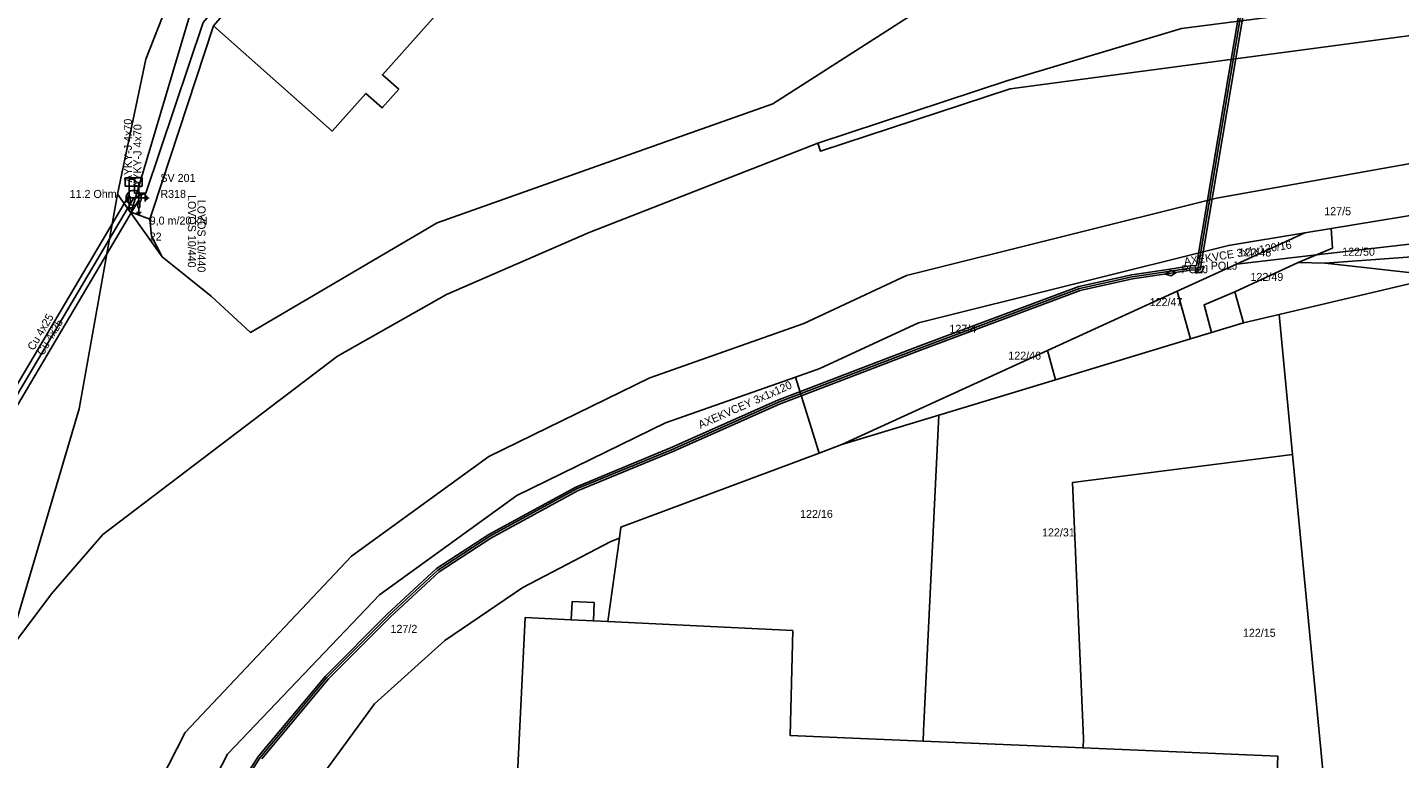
# Model space of a CAD drawing. Extents: x -793400 to -756198, y -1074141 to -1042963.
# Drawn here: x -783476.3 to -783347.8, y -1064939.5 to -1064870.9 of the extents above; entities that cross this region are included whole.
import ezdxf

# ---------------------------------------------------------------- set-up
doc = ezdxf.new("R2010")
doc.units = 0
for name, color, linetype in [('Parcela', 7, 'Continuous'), ('PB nn', 7, 'Continuous'), ('Popiskový text - Parcela', 7, 'Continuous'), ('Popiskový text - PB nn - sk_1 - SJZ', 7, 'Continuous'), ('Popiskový text - PB nn - sk_1 - Výška_Tahové namáhání', 7, 'Continuous'), ('Popiskový text - Rozpojovací skříň nn - SJZ', 7, 'Continuous'), ('Popiskový text - Rozpojovací skříň nn - Typ', 7, 'Continuous'), ('Popiskový text - Spojka vn - Typ', 7, 'Continuous'), ('Popiskový text - Svodič nn - Typ', 7, 'Continuous'), ('Popiskový text - Uzemnění - Odpor', 7, 'Continuous'), ('Popiskový text - Vedení nn svod', 7, 'Continuous'), ('Popiskový text - Vedení nn venkovní', 7, 'Continuous'), ('Popiskový text - Vedení vn kabelové', 7, 'Continuous'), ('Skříň', 7, 'Continuous'), ('Spojka vn', 7, 'Continuous'), ('Spojnice nn', 7, 'Continuous'), ('Spojnice vn', 7, 'Continuous'), ('Stavební objekt', 7, 'Continuous'), ('Svodič nn', 7, 'Continuous'), ('Uzemnění', 7, 'Continuous'), ('Vedení 22 kV kabelové', 7, 'Continuous'), ('Vedení nn kabelové', 7, 'Continuous'), ('Vedení nn svod', 7, 'Continuous'), ('Vedení nn venkovní', 7, 'Continuous')]:
    doc.layers.add(name, color=color, linetype=linetype)

msp = doc.modelspace()

# ---------------------------------------------------------------- linework, layer by layer
at = {"layer": 'Parcela'}
for points in [[(-783338.48, -1064697.96), (-783349.27, -1064716.7), (-783367.16, -1064741.51), (-783384.84, -1064768.74), (-783393.05, -1064780.33), (-783390.82, -1064782.2), (-783435.82, -1064826.87), (-783453.88, -1064848.76), (-783461.77, -1064865.05), (-783465.25, -1064873.91), (-783467.9, -1064886.57), (-783471.49, -1064906.69), (-783478.28, -1064929.62), (-783482.83, -1064940.99)], [(-783482.83, -1064940.99), (-783478.28, -1064929.62), (-783474.07, -1064924.03), (-783469.27, -1064918.46), (-783447.3, -1064901.74), (-783437.08, -1064895.97), (-783423.7, -1064890.15), (-783407.72, -1064883.89), (-783402.29, -1064881.78), (-783402.03, -1064882.54), (-783384.26, -1064876.67), (-783335.01, -1064870.13), (-783304.09, -1064866.02), (-783285.91, -1064866.45), (-783278.18, -1064867.77), (-783223.32, -1064876.5)], [(-783227.58, -1064889.71), (-783274.38, -1064881.1), (-783287.03, -1064879.4), (-783307.17, -1064880.57), (-783332.97, -1064881.2), (-783364.93, -1064886.92), (-783393.97, -1064894.19), (-783403.59, -1064898.67), (-783418.04, -1064903.77), (-783433.11, -1064911.15), (-783445.96, -1064920.48), (-783461.55, -1064937.01), (-783469.34, -1064952.28)], [(-783469.34, -1064952.28), (-783461.55, -1064937.01), (-783445.96, -1064920.48), (-783433.11, -1064911.15), (-783418.04, -1064903.77), (-783403.59, -1064898.67), (-783393.97, -1064894.19), (-783364.93, -1064886.92), (-783332.97, -1064881.2), (-783307.17, -1064880.57), (-783287.03, -1064879.4), (-783274.38, -1064881.1), (-783227.58, -1064889.71)], [(-783225.68, -1064895.58), (-783274.99, -1064885.59), (-783280.75, -1064884.81), (-783287.64, -1064883.89), (-783306.72, -1064885.08), (-783332, -1064887.64), (-783332.16, -1064886.15), (-783354.2, -1064889.78), (-783356.67, -1064890.19), (-783363.82, -1064891.36), (-783392.86, -1064898.63), (-783402.1, -1064902.9), (-783404.39, -1064903.71), (-783416.55, -1064908), (-783430.48, -1064914.8), (-783443.35, -1064924.13), (-783457.58, -1064939.04), (-783464.9, -1064953.22)], [(-783353.28, -1064958.14), (-783357.81, -1064910.97), (-783359.07, -1064897.84), (-783343.83, -1064894.26), (-783331.24, -1064891.31), (-783281.17, -1064887.87), (-783279.74, -1064888.31), (-783222.97, -1064905.78)], [(-783464.9, -1064953.22), (-783457.58, -1064939.04), (-783443.35, -1064924.13), (-783430.48, -1064914.8), (-783416.55, -1064908), (-783404.39, -1064903.71), (-783402.17, -1064910.83), (-783420.73, -1064917.76), (-783420.88, -1064918.79), (-783421.67, -1064919.12), (-783429.93, -1064923.44), (-783437.22, -1064928.4), (-783443.83, -1064934.34), (-783449.41, -1064942)], [(-783449.41, -1064942), (-783443.83, -1064934.34), (-783437.22, -1064928.4), (-783429.93, -1064923.44), (-783421.67, -1064919.12), (-783420.88, -1064918.79), (-783421.96, -1064926.63), (-783423.31, -1064926.56), (-783423.23, -1064924.85), (-783425.3, -1064924.75), (-783425.39, -1064926.46), (-783429.7, -1064926.25), (-783430.41, -1064940.93)]]:
    msp.add_lwpolyline(points, dxfattribs=at)
for points in [[(-783385.6, -1064832.92), (-783375.04, -1064846.09), (-783368.94, -1064842.22), (-783364, -1064850.02), (-783360.4, -1064848.81), (-783374.34, -1064857.56), (-783381.42, -1064862.01), (-783383.2, -1064863.13), (-783391.14, -1064868.23), (-783406.49, -1064878.08), (-783414.73, -1064881.01), (-783437.94, -1064889.26), (-783455.45, -1064899.52), (-783459.11, -1064896.13), (-783463.71, -1064892.42), (-783464.71, -1064890.5), (-783464.87, -1064888.91), (-783464.59, -1064888.07), (-783458.89, -1064870.77), (-783415.27, -1064820.68), (-783417.8, -1064816.8), (-783413.58, -1064811.55), (-783393.24, -1064823.15), (-783383.11, -1064830.7)], [(-783417.8, -1064816.8), (-783415.27, -1064820.68), (-783417.18, -1064818.99), (-783461.16, -1064869.86), (-783466.61, -1064888.26), (-783464.87, -1064888.91), (-783464.71, -1064890.5), (-783463.71, -1064892.42), (-783467.9, -1064886.57), (-783465.25, -1064873.91), (-783461.77, -1064865.05), (-783453.88, -1064848.76), (-783451.28, -1064850.75), (-783448.79, -1064853.49)], [(-783464.59, -1064888.07), (-783464.87, -1064888.91), (-783466.61, -1064888.26), (-783461.16, -1064869.86), (-783417.18, -1064818.99), (-783415.27, -1064820.68), (-783458.89, -1064870.77)], [(-783437.08, -1064895.97), (-783447.3, -1064901.74), (-783469.27, -1064918.46), (-783474.07, -1064924.03), (-783478.28, -1064929.62), (-783471.49, -1064906.69), (-783467.9, -1064886.57), (-783463.71, -1064892.42), (-783459.11, -1064896.13), (-783455.45, -1064899.52), (-783437.94, -1064889.26), (-783414.73, -1064881.01), (-783406.49, -1064878.08), (-783391.14, -1064868.23), (-783383.2, -1064863.13), (-783381.42, -1064862.01), (-783374.34, -1064857.56), (-783360.4, -1064848.81), (-783352.38, -1064869), (-783368.2, -1064871.03), (-783384.5, -1064875.9), (-783402.29, -1064881.78), (-783407.72, -1064883.89), (-783423.7, -1064890.15)], [(-783269.29, -1064864.07), (-783252.64, -1064867.19), (-783241.36, -1064869.64), (-783217.15, -1064873.79), (-783212.94, -1064874.09), (-783223.32, -1064876.5), (-783278.18, -1064867.77), (-783285.91, -1064866.45), (-783304.09, -1064866.02), (-783335.01, -1064870.13), (-783384.26, -1064876.67), (-783402.03, -1064882.54), (-783402.29, -1064881.78), (-783384.5, -1064875.9), (-783368.2, -1064871.03), (-783352.38, -1064869), (-783335.67, -1064866.45), (-783335.87, -1064864.4), (-783303.98, -1064861.03), (-783285.8, -1064861.46), (-783277.41, -1064862.75)], [(-783280.75, -1064884.81), (-783279.77, -1064888.22), (-783279.74, -1064888.31), (-783281.17, -1064887.87), (-783331.24, -1064891.31), (-783354.76, -1064893.04), (-783357.29, -1064892.97), (-783355.58, -1064892.25), (-783339.48, -1064890.4), (-783284.2, -1064887.63)], [(-783284.2, -1064887.63), (-783339.48, -1064890.4), (-783355.58, -1064892.25), (-783354.08, -1064891.62), (-783354.2, -1064889.78), (-783332.16, -1064886.15), (-783332, -1064887.64), (-783306.72, -1064885.08), (-783287.64, -1064883.89), (-783280.75, -1064884.81)], [(-783400.04, -1064910.03), (-783402.17, -1064910.83), (-783404.39, -1064903.71), (-783402.1, -1064902.9), (-783392.86, -1064898.63), (-783363.82, -1064891.36), (-783356.67, -1064890.19), (-783363.06, -1064893.11), (-783368.63, -1064895.66), (-783380.77, -1064901.21)], [(-783355.58, -1064892.25), (-783363.06, -1064893.11), (-783356.67, -1064890.19), (-783354.2, -1064889.78), (-783354.08, -1064891.62)], [(-783331.24, -1064891.31), (-783343.83, -1064894.26), (-783354.76, -1064893.04)], [(-783365.39, -1064899.53), (-783367.37, -1064900.13), (-783368.63, -1064895.66), (-783363.06, -1064893.11), (-783355.58, -1064892.25), (-783357.29, -1064892.97), (-783363.23, -1064895.71), (-783366.1, -1064896.94)], [(-783359.07, -1064897.84), (-783362.4, -1064898.62), (-783363.23, -1064895.71), (-783357.29, -1064892.97), (-783354.76, -1064893.04), (-783343.83, -1064894.26)], [(-783367.37, -1064900.13), (-783380.01, -1064903.96), (-783380.77, -1064901.21), (-783368.63, -1064895.66)], [(-783362.4, -1064898.62), (-783365.39, -1064899.53), (-783366.1, -1064896.94), (-783363.23, -1064895.71)], [(-783377.4, -1064937.59), (-783377.44, -1064938.46), (-783392.43, -1064937.82), (-783392.38, -1064936.86), (-783390.94, -1064907.27), (-783380.01, -1064903.96), (-783367.37, -1064900.13), (-783365.39, -1064899.53), (-783362.4, -1064898.62), (-783359.07, -1064897.84), (-783357.81, -1064910.97), (-783378.43, -1064913.59)], [(-783390.94, -1064907.27), (-783400.04, -1064910.03), (-783380.77, -1064901.21), (-783380.01, -1064903.96)], [(-783392.38, -1064936.86), (-783392.43, -1064937.82), (-783404.88, -1064937.3), (-783404.64, -1064927.47), (-783421.96, -1064926.63), (-783420.88, -1064918.79), (-783420.73, -1064917.76), (-783402.17, -1064910.83), (-783400.04, -1064910.03), (-783390.94, -1064907.27)], [(-783356.71, -1064964.98), (-783360.26, -1064964.99), (-783359.2, -1064939.23), (-783377.44, -1064938.46), (-783377.4, -1064937.59), (-783378.43, -1064913.59), (-783357.81, -1064910.97), (-783353.28, -1064958.14), (-783354.18, -1064962.02)], [(-783423.23, -1064924.85), (-783423.31, -1064926.56), (-783421.96, -1064926.63), (-783404.64, -1064927.47), (-783404.88, -1064937.3), (-783392.43, -1064937.82), (-783377.44, -1064938.46), (-783359.2, -1064939.23), (-783360.26, -1064964.99), (-783360.34, -1064966.94), (-783408.79, -1064964.93), (-783408.66, -1064962.07), (-783416.86, -1064961.75), (-783416.9, -1064962.62), (-783419.02, -1064962.53), (-783418.98, -1064961.67), (-783431.4, -1064961.19), (-783430.84, -1064949.72), (-783433.81, -1064949.58), (-783433.38, -1064940.79), (-783430.41, -1064940.93), (-783429.7, -1064926.25), (-783425.39, -1064926.46), (-783425.3, -1064924.75)]]:
    msp.add_lwpolyline(points, close=True, dxfattribs=at)
at = {"layer": 'PB nn'}
msp.add_line((-783465.67, -1064886.91), (-783467.09, -1064886.91), dxfattribs=at)
for start, end in [(0, 180), (180, 0)]:
    msp.add_arc((-783466.38, -1064886.91), 0.709, start, end, dxfattribs=at)
at = {"layer": 'Skříň'}
msp.add_lwpolyline([(-783467.17, -1064885.02), (-783465.59, -1064885.02), (-783465.59, -1064885.8), (-783467.17, -1064885.8)], close=True, dxfattribs=at)
at = {"layer": 'Spojka vn'}
for points in [[(-783368.72, -1064893.89), (-783369.26, -1064893.72), (-783369.71, -1064894.05), (-783369.18, -1064894.22)], [(-783366.1, -1064893.31), (-783366.64, -1064893.45), (-783366.86, -1064893.97), (-783366.32, -1064893.83)]]:
    msp.add_lwpolyline(points, close=True, dxfattribs=at)
at = {"layer": 'Spojnice nn'}
msp.add_line((-783483.8, -1064916.34), (-783466.38, -1064886.91), dxfattribs=at)
msp.add_lwpolyline([(-783466.38, -1064886.91), (-783465.23, -1064886.46), (-783459.87, -1064870.48), (-783448.33, -1064856.95), (-783441.33, -1064848.51)], dxfattribs=at)
at = {"layer": 'Spojnice vn'}
for points in [[(-783362.08, -1064866.35), (-783366.65, -1064893.45)], [(-783369.25, -1064893.77), (-783372.84, -1064894.32), (-783377.78, -1064895.4), (-783392.73, -1064901), (-783405.96, -1064906.06), (-783416, -1064910.52), (-783424.88, -1064914.19), (-783433.01, -1064918.63), (-783437.9, -1064921.81), (-783442.48, -1064926.06), (-783448.27, -1064931.87), (-783454.54, -1064939.37), (-783458.76, -1064945.94)], [(-783366.65, -1064893.45), (-783367.39, -1064893.48), (-783369.25, -1064893.77)]]:
    msp.add_lwpolyline(points, dxfattribs=at)
at = {"layer": 'Stavební objekt'}
for points in [[(-783397.33, -1064836.53), (-783406.3, -1064847), (-783413.04, -1064841.14), (-783420.03, -1064849.51), (-783415.73, -1064853.11), (-783422.67, -1064861.15), (-783427.04, -1064857.37), (-783443.08, -1064875.37), (-783441.55, -1064876.73), (-783443.1, -1064878.47), (-783444.63, -1064877.11), (-783447.79, -1064880.65), (-783458.89, -1064870.77), (-783415.27, -1064820.68)], [(-783360.26, -1064964.99), (-783360.34, -1064966.94), (-783408.79, -1064964.93), (-783408.66, -1064962.07), (-783416.86, -1064961.75), (-783418.98, -1064961.67), (-783431.4, -1064961.19), (-783430.84, -1064949.72), (-783430.41, -1064940.93), (-783429.7, -1064926.25), (-783425.39, -1064926.46), (-783423.31, -1064926.56), (-783421.96, -1064926.63), (-783404.64, -1064927.47), (-783404.88, -1064937.3), (-783392.43, -1064937.82), (-783377.44, -1064938.46), (-783359.2, -1064939.23)]]:
    msp.add_lwpolyline(points, close=True, dxfattribs=at)
at = {"layer": 'Svodič nn'}
for p, q in [((-783466.9, -1064887.36), (-783466.9, -1064886.77)), ((-783466.9, -1064886.77), (-783466.7, -1064886.77)), ((-783466.7, -1064887.36), (-783466.9, -1064887.36)), ((-783466.8, -1064886.64), (-783466.8, -1064886.84)), ((-783466.8, -1064887.36), (-783466.8, -1064887.84)), ((-783466.7, -1064886.77), (-783466.7, -1064887.36)), ((-783466, -1064887.81), (-783466, -1064887.22)), ((-783466, -1064887.22), (-783465.8, -1064887.22)), ((-783465.9, -1064887.08), (-783465.9, -1064887.29)), ((-783465.8, -1064887.22), (-783465.8, -1064887.81)), ((-783467.02, -1064887.84), (-783466.58, -1064887.84)), ((-783466.94, -1064887.94), (-783466.66, -1064887.94)), ((-783466.85, -1064888.05), (-783466.75, -1064888.05)), ((-783466.12, -1064888.29), (-783465.68, -1064888.29)), ((-783466.04, -1064888.38), (-783465.76, -1064888.39)), ((-783465.8, -1064887.81), (-783466, -1064887.81)), ((-783465.95, -1064888.49), (-783465.85, -1064888.49)), ((-783465.9, -1064887.81), (-783465.9, -1064888.29))]:
    msp.add_line(p, q, dxfattribs=at)
for points in [[(-783466.8, -1064886.95), (-783466.73, -1064886.84), (-783466.87, -1064886.84)], [(-783465.9, -1064887.39), (-783465.83, -1064887.29), (-783465.97, -1064887.29)]]:
    msp.add_lwpolyline(points, close=True, dxfattribs=at)
at = {"layer": 'Uzemnění'}
for p, q in [((-783465.99, -1064886.91), (-783465.3, -1064886.91)), ((-783465.3, -1064887.26), (-783465.3, -1064886.56)), ((-783465.21, -1064887.13), (-783465.21, -1064886.69)), ((-783465.11, -1064887.05), (-783465.11, -1064886.77)), ((-783465, -1064886.96), (-783465, -1064886.86))]:
    msp.add_line(p, q, dxfattribs=at)
at = {"layer": 'Vedení 22 kV kabelové'}
for points in [[(-783362.28, -1064866.3), (-783366.82, -1064893.25), (-783367.41, -1064893.28), (-783369.28, -1064893.58), (-783372.88, -1064894.12), (-783377.84, -1064895.2), (-783392.81, -1064900.81), (-783406.04, -1064905.88), (-783416.08, -1064910.34), (-783424.96, -1064914.01), (-783433.11, -1064918.46), (-783438.02, -1064921.65), (-783442.62, -1064925.92), (-783448.41, -1064931.73), (-783454.7, -1064939.25), (-783458.94, -1064945.85)], [(-783361.89, -1064866.39), (-783366.48, -1064893.64)], [(-783369.22, -1064893.97), (-783372.8, -1064894.51), (-783377.72, -1064895.59), (-783392.66, -1064901.18), (-783405.88, -1064906.25), (-783415.92, -1064910.71), (-783424.79, -1064914.37), (-783432.91, -1064918.81), (-783437.77, -1064921.97), (-783442.34, -1064926.21), (-783448.12, -1064932), (-783454.38, -1064939.49)], [(-783366.48, -1064893.64), (-783367.37, -1064893.68), (-783369.22, -1064893.97)]]:
    msp.add_lwpolyline(points, dxfattribs=at)
at = {"layer": 'Vedení nn kabelové'}
msp.add_lwpolyline([(-783466.29, -1064885.61), (-783466.29, -1064886.46), (-783465.23, -1064886.46), (-783459.87, -1064870.48), (-783448.33, -1064856.95), (-783441.71, -1064848.97), (-783440.69, -1064849.85), (-783440.1, -1064849.85), (-783440.1, -1064849.49)], dxfattribs=at)
at = {"layer": 'Vedení nn svod'}
for points in [[(-783466.8, -1064886.64), (-783466.8, -1064885.14), (-783466.29, -1064885.14), (-783466.29, -1064885.5)], [(-783465.9, -1064887.08), (-783465.9, -1064885.58), (-783466.27, -1064885.26), (-783466.27, -1064885.5)]]:
    msp.add_lwpolyline(points, dxfattribs=at)
at = {"layer": 'Vedení nn venkovní'}
for points in [[(-783483.8, -1064916.34), (-783483.51, -1064914.87), (-783466.8, -1064886.64)], [(-783483.8, -1064916.34), (-783482.58, -1064915.26), (-783465.9, -1064887.08)]]:
    msp.add_lwpolyline(points, dxfattribs=at)

# ---------------------------------------------------------------- texts
at = {"layer": 'Popiskový text - Parcela'}
for s, p in [('127/5', (-783354.84, -1064888.53)), ('122/50', (-783353.16, -1064892.33)), ('122/48', (-783362.87, -1064892.4)), ('122/49', (-783361.75, -1064894.69)), ('122/47', (-783371.2, -1064897.05)), ('127/4', (-783389.96, -1064899.55)), ('122/46', (-783384.44, -1064902.07)), ('122/16', (-783403.95, -1064916.91)), ('122/31', (-783381.28, -1064918.64)), ('127/2', (-783442.32, -1064927.68)), ('122/15', (-783362.46, -1064928.05))]:
    msp.add_text(s, height=0.75, dxfattribs=at).set_placement(p)
at = {"layer": 'Popiskový text - PB nn - sk_1 - SJZ'}
msp.add_text('22', height=0.75, dxfattribs=at).set_placement((-783464.88, -1064890.91))
at = {"layer": 'Popiskový text - PB nn - sk_1 - Výška_Tahové namáhání'}
msp.add_text('9,0 m/20 kN', height=0.75, dxfattribs=at).set_placement((-783464.88, -1064889.41))
at = {"layer": 'Popiskový text - Rozpojovací skříň nn - SJZ'}
msp.add_text('R318', height=0.75, dxfattribs=at).set_placement((-783463.88, -1064886.91))
at = {"layer": 'Popiskový text - Rozpojovací skříň nn - Typ'}
msp.add_text('SV 201', height=0.75, dxfattribs=at).set_placement((-783463.88, -1064885.41))
at = {"layer": 'Popiskový text - Spojka vn - Typ'}
for p in [(-783368.22, -1064893.97), (-783365.48, -1064893.64)]:
    msp.add_text('POLJ', height=0.75, dxfattribs=at).set_placement(p)
at = {"layer": 'Popiskový text - Svodič nn - Typ'}
for p in [(-783461.3, -1064886.64), (-783460.4, -1064887.08)]:
    msp.add_text('LOVOS 10/440', height=0.75, rotation=269.9777, dxfattribs=at).set_placement(p)
at = {"layer": 'Popiskový text - Uzemnění - Odpor'}
msp.add_text('11.2 Ohm', height=0.75, dxfattribs=at).set_placement((-783472.38, -1064886.91))
at = {"layer": 'Popiskový text - Vedení nn svod'}
for p in [(-783466.55, -1064885.45), (-783465.65, -1064885.97)]:
    msp.add_text('AYKY-J 4x70', height=0.75, rotation=90.0117, dxfattribs=at).set_placement(p)
at = {"layer": 'Popiskový text - Vedení nn venkovní'}
for p in [(-783475.75, -1064901.27), (-783474.87, -1064901.75)]:
    msp.add_text('Cu 4x25', height=0.75, rotation=59.3584, dxfattribs=at).set_placement(p)
at = {"layer": 'Popiskový text - Vedení vn kabelové'}
for s, rotation, p in [('AXEKVCE 3x1x120/16', 9.11, (-783367.93, -1064893.26)), ('AXEKVCEY 3x1x120', 23.9496, (-783413.29, -1064908.56))]:
    msp.add_text(s, height=0.75, rotation=rotation, dxfattribs=at).set_placement(p)
at = {"layer": 'Skříň'}
msp.add_text('PB', height=0.1, dxfattribs=at).set_placement((-783467.11, -1064885.17))

doc.saveas('drawing.dxf')
